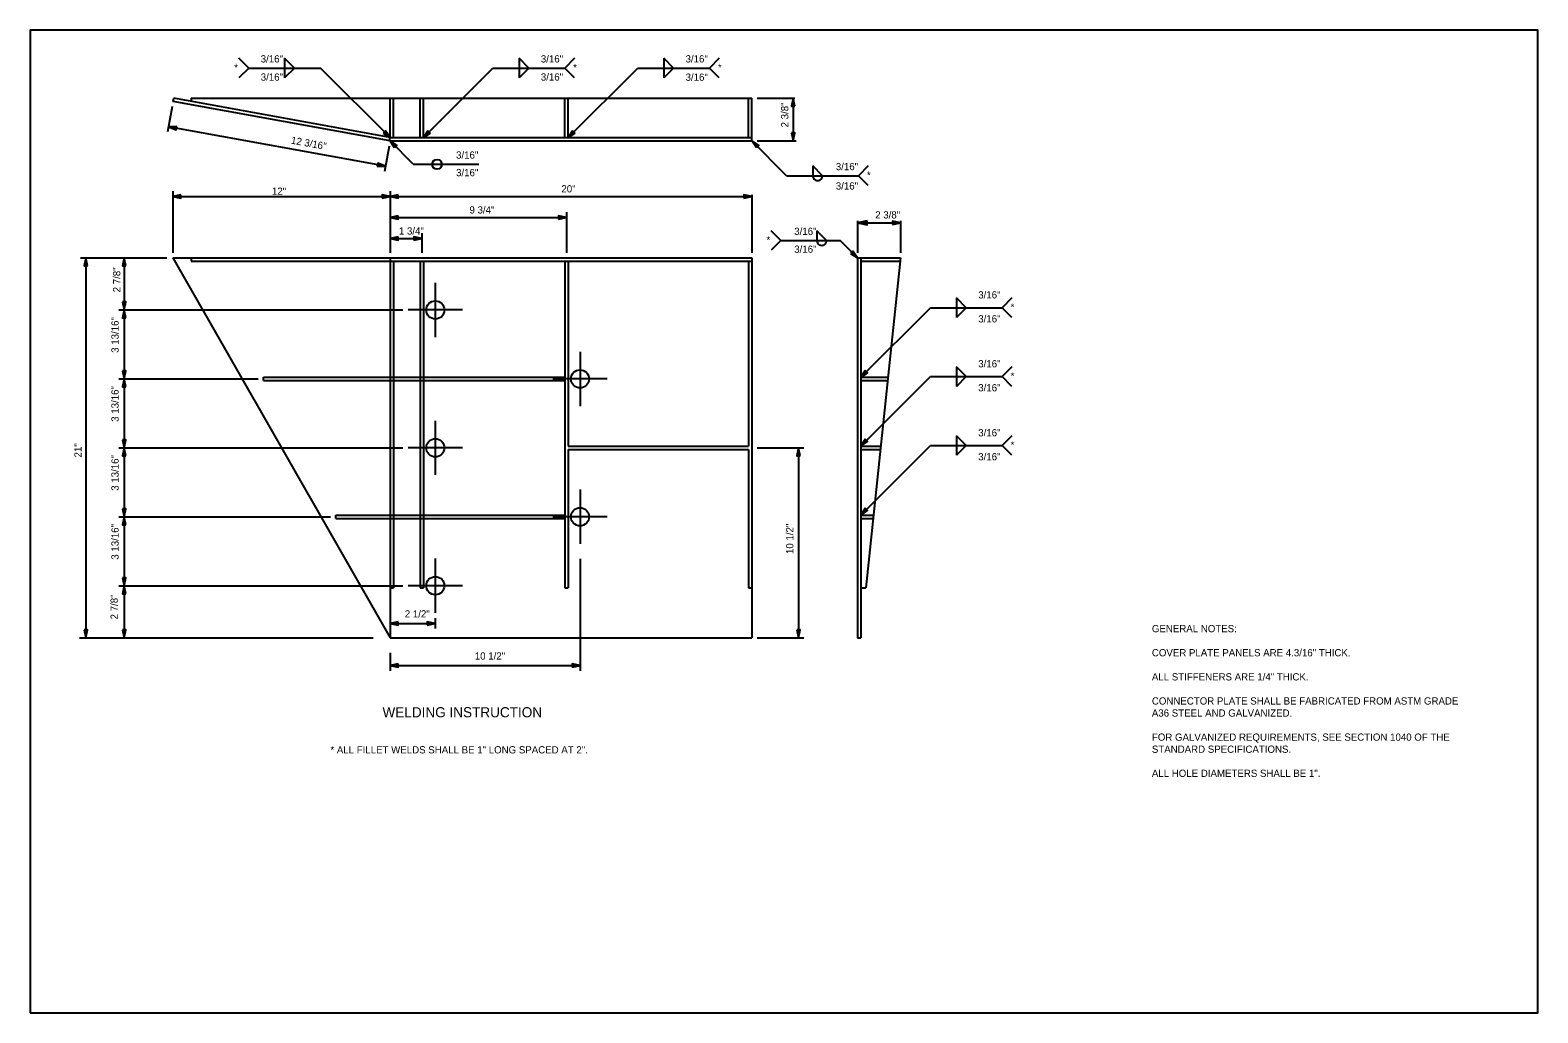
# Model space of a CAD drawing. Extents: x -439.1 to -407.9, y -458.1 to -437.7.
import ezdxf

# ---------------------------------------------------------------- set-up
doc = ezdxf.new("R2010")
doc.units = 0
for name, color, linetype in [('Common-Notes', 7, 'Continuous'), ('Draft_Named_Boundary', 7, 'Continuous'), ('Level 4', 7, 'Continuous'), ('Level 45', 7, 'Continuous')]:
    doc.layers.add(name, color=color, linetype=linetype)

msp = doc.modelspace()

# ---------------------------------------------------------------- linework, layer by layer
at = {"layer": 'Draft_Named_Boundary'}
msp.add_lwpolyline([(-439.109, -458.051), (-407.859, -458.051), (-407.859, -437.676), (-439.109, -437.676)], close=True, dxfattribs=at)
at = {"layer": 'Level 4'}
for p, q in [((-434.579, -438.462), (-434.781, -438.26)), ((-433.835, -438.26), (-433.835, -438.664)), ((-433.633, -438.462), (-433.835, -438.26)), ((-428.974, -438.26), (-428.974, -438.664)), ((-428.772, -438.462), (-428.974, -438.26)), ((-427.827, -438.26), (-428.028, -438.462)), ((-425.974, -438.26), (-425.974, -438.664)), ((-425.772, -438.462), (-425.974, -438.26)), ((-424.827, -438.26), (-425.028, -438.462)), ((-434.579, -438.462), (-434.781, -438.664)), ((-434.579, -438.462), (-433.091, -438.462)), ((-433.633, -438.462), (-433.835, -438.664)), ((-431.649, -439.903), (-433.091, -438.462)), ((-430.958, -439.903), (-429.516, -438.462)), ((-429.516, -438.462), (-428.028, -438.462)), ((-428.772, -438.462), (-428.974, -438.664)), ((-427.827, -438.664), (-428.028, -438.462)), ((-427.958, -439.903), (-426.516, -438.462)), ((-426.516, -438.462), (-425.028, -438.462)), ((-425.772, -438.462), (-425.974, -438.664)), ((-424.827, -438.664), (-425.028, -438.462)), ((-436.165, -439.262), (-436.26, -439.786)), ((-436.145, -439.154), (-436.133, -439.087)), ((-431.649, -439.973), (-436.145, -439.154)), ((-431.649, -439.903), (-436.133, -439.087)), ((-435.774, -439.083), (-424.149, -439.083)), ((-435.774, -439.083), (-435.774, -439.152)), ((-431.649, -439.903), (-431.649, -439.083)), ((-431.579, -439.903), (-431.579, -439.083)), ((-431.028, -439.903), (-431.028, -439.083)), ((-430.958, -439.903), (-430.958, -439.083)), ((-428.028, -439.903), (-428.028, -439.083)), ((-427.958, -439.903), (-427.958, -439.083)), ((-424.22, -439.903), (-424.22, -439.083)), ((-424.149, -439.973), (-424.149, -439.083)), ((-424.041, -439.083), (-423.257, -439.083)), ((-423.291, -439.083), (-423.291, -439.973)), ((-431.745, -440.498), (-436.241, -439.679)), ((-431.662, -439.971), (-431.649, -439.903)), ((-431.649, -439.903), (-424.149, -439.903)), ((-431.649, -439.973), (-424.149, -439.973)), ((-431.167, -440.456), (-431.649, -439.973)), ((-423.429, -440.694), (-424.149, -439.973)), ((-424.041, -439.973), (-423.231, -439.973)), ((-431.669, -440.081), (-431.764, -440.605)), ((-431.167, -440.456), (-429.812, -440.456)), ((-422.887, -440.492), (-422.887, -440.694)), ((-422.685, -440.694), (-422.887, -440.492)), ((-421.739, -440.492), (-421.941, -440.694)), ((-423.429, -440.694), (-421.941, -440.694)), ((-421.739, -440.896), (-421.941, -440.694)), ((-436.149, -441.015), (-436.149, -442.29)), ((-436.149, -441.124), (-431.649, -441.124)), ((-431.649, -441.015), (-431.649, -442.29)), ((-431.649, -441.124), (-424.149, -441.124)), ((-424.149, -441.089), (-424.149, -442.29)), ((-431.649, -441.559), (-427.993, -441.559)), ((-427.993, -441.45), (-427.993, -442.29)), ((-423.547, -442.038), (-423.749, -441.836)), ((-422.803, -441.836), (-422.803, -442.038)), ((-422.601, -442.038), (-422.803, -441.836)), ((-421.962, -441.627), (-421.962, -442.29)), ((-421.962, -441.668), (-421.072, -441.668)), ((-421.072, -441.627), (-421.072, -442.29)), ((-431.649, -441.995), (-430.993, -441.995)), ((-430.993, -441.886), (-430.993, -442.29)), ((-423.547, -442.038), (-423.749, -442.24)), ((-423.547, -442.038), (-422.323, -442.038)), ((-421.962, -442.399), (-422.323, -442.038)), ((-438.065, -442.399), (-436.275, -442.399)), ((-437.956, -442.399), (-437.956, -450.274)), ((-437.159, -442.399), (-437.159, -443.477)), ((-436.149, -442.399), (-431.649, -442.399)), ((-436.149, -442.399), (-431.649, -450.274)), ((-435.774, -442.399), (-435.774, -442.469)), ((-435.774, -442.469), (-431.649, -442.469)), ((-431.649, -442.399), (-424.149, -442.399)), ((-431.649, -442.399), (-431.649, -450.274)), ((-431.649, -442.469), (-424.149, -442.469)), ((-431.579, -442.469), (-431.579, -449.242)), ((-431.028, -442.469), (-431.028, -449.242)), ((-430.958, -442.469), (-430.958, -449.242)), ((-428.028, -442.469), (-428.028, -449.242)), ((-427.958, -442.469), (-427.958, -446.301)), ((-424.22, -442.469), (-424.22, -446.301)), ((-424.149, -442.399), (-424.149, -450.274)), ((-421.962, -442.399), (-421.962, -450.274)), ((-421.962, -442.399), (-421.072, -442.399)), ((-421.892, -442.399), (-421.892, -450.274)), ((-421.892, -442.469), (-421.072, -442.469)), ((-421.072, -442.399), (-421.785, -449.242)), ((-430.712, -442.914), (-430.712, -444.039)), ((-421.892, -444.871), (-420.45, -443.43)), ((-420.45, -443.43), (-418.962, -443.43)), ((-419.908, -443.228), (-419.908, -443.632)), ((-419.706, -443.43), (-419.908, -443.228)), ((-419.706, -443.43), (-419.908, -443.632)), ((-418.761, -443.228), (-418.962, -443.43)), ((-418.761, -443.632), (-418.962, -443.43)), ((-437.268, -443.477), (-431.383, -443.477)), ((-437.159, -443.477), (-437.159, -444.907)), ((-430.149, -443.477), (-431.274, -443.477)), ((-427.712, -444.344), (-427.712, -445.469)), ((-419.908, -444.657), (-419.908, -445.061)), ((-419.706, -444.859), (-419.908, -444.657)), ((-418.761, -444.657), (-418.962, -444.859)), ((-437.268, -444.907), (-434.383, -444.907)), ((-437.159, -444.907), (-437.159, -446.336)), ((-434.274, -444.871), (-428.028, -444.871)), ((-434.274, -444.942), (-434.274, -444.871)), ((-434.274, -444.942), (-428.028, -444.942)), ((-427.149, -444.907), (-428.274, -444.907)), ((-421.892, -446.301), (-420.45, -444.859)), ((-421.892, -444.871), (-421.329, -444.871)), ((-421.892, -444.942), (-421.329, -444.942)), ((-420.45, -444.859), (-418.962, -444.859)), ((-419.706, -444.859), (-419.908, -445.061)), ((-418.761, -445.061), (-418.962, -444.859)), ((-430.712, -445.774), (-430.712, -446.899)), ((-419.908, -446.087), (-419.908, -446.491)), ((-419.706, -446.289), (-419.908, -446.087)), ((-418.761, -446.087), (-418.962, -446.289)), ((-437.268, -446.336), (-431.383, -446.336)), ((-437.159, -446.336), (-437.159, -447.766)), ((-430.149, -446.336), (-431.274, -446.336)), ((-427.958, -446.301), (-424.22, -446.301)), ((-427.958, -446.371), (-424.22, -446.371)), ((-427.958, -446.371), (-427.958, -449.242)), ((-424.22, -446.371), (-424.22, -449.242)), ((-424.041, -446.336), (-423.074, -446.336)), ((-423.183, -446.336), (-423.183, -450.274)), ((-421.892, -447.73), (-420.45, -446.289)), ((-421.892, -446.301), (-421.478, -446.301)), ((-421.892, -446.371), (-421.485, -446.371)), ((-420.45, -446.289), (-418.962, -446.289)), ((-419.706, -446.289), (-419.908, -446.491)), ((-418.761, -446.491), (-418.962, -446.289)), ((-427.712, -447.203), (-427.712, -448.328)), ((-437.268, -447.766), (-432.883, -447.766)), ((-437.159, -447.766), (-437.159, -449.195)), ((-432.774, -447.73), (-428.028, -447.73)), ((-432.774, -447.801), (-432.774, -447.73)), ((-432.774, -447.801), (-428.028, -447.801)), ((-427.149, -447.766), (-428.274, -447.766)), ((-421.892, -447.73), (-421.627, -447.73)), ((-421.892, -447.801), (-421.635, -447.801)), ((-430.712, -448.633), (-430.712, -449.758)), ((-427.712, -448.64), (-427.712, -450.959)), ((-437.268, -449.195), (-431.383, -449.195)), ((-437.159, -449.195), (-437.159, -450.274)), ((-431.649, -449.242), (-431.579, -449.242)), ((-430.149, -449.195), (-431.274, -449.195)), ((-431.028, -449.242), (-430.958, -449.242)), ((-428.028, -449.242), (-427.958, -449.242)), ((-424.22, -449.242), (-424.149, -449.242)), ((-421.892, -449.242), (-421.785, -449.242)), ((-431.649, -449.975), (-430.712, -449.975)), ((-430.712, -449.866), (-430.712, -450.084)), ((-438.084, -450.275), (-431.997, -450.275)), ((-431.649, -450.274), (-424.149, -450.274)), ((-424.041, -450.274), (-423.074, -450.274)), ((-421.962, -450.274), (-421.892, -450.274)), ((-431.649, -450.586), (-431.649, -450.959)), ((-431.649, -450.85), (-427.712, -450.85))]:
    msp.add_line(p, q, dxfattribs=at)
for points in [[(-423.257, -439.249), (-423.291, -439.083), (-423.326, -439.249)], [(-436.072, -439.675), (-436.241, -439.679), (-436.084, -439.742)], [(-431.791, -439.81), (-431.649, -439.903), (-431.742, -439.762)], [(-431.556, -440.115), (-431.649, -439.973), (-431.508, -440.066)], [(-430.865, -439.762), (-430.958, -439.903), (-430.816, -439.81)], [(-427.865, -439.762), (-427.958, -439.903), (-427.816, -439.81)], [(-424.056, -440.115), (-424.149, -439.973), (-424.008, -440.066)], [(-423.326, -439.808), (-423.291, -439.973), (-423.257, -439.808)], [(-431.914, -440.502), (-431.745, -440.498), (-431.902, -440.434)], [(-435.983, -441.089), (-436.149, -441.124), (-435.983, -441.158)], [(-431.815, -441.158), (-431.649, -441.124), (-431.815, -441.089)], [(-431.483, -441.089), (-431.649, -441.124), (-431.483, -441.158)], [(-424.315, -441.158), (-424.149, -441.124), (-424.315, -441.089)], [(-431.483, -441.525), (-431.649, -441.559), (-431.483, -441.594)], [(-428.159, -441.594), (-427.993, -441.559), (-428.159, -441.525)], [(-421.763, -441.627), (-421.962, -441.668), (-421.763, -441.709)], [(-421.238, -441.703), (-421.072, -441.668), (-421.238, -441.634)], [(-431.483, -441.96), (-431.649, -441.995), (-431.483, -442.029)], [(-431.159, -442.029), (-430.993, -441.995), (-431.159, -441.96)], [(-437.921, -442.565), (-437.956, -442.399), (-437.99, -442.565)], [(-437.124, -442.565), (-437.159, -442.399), (-437.193, -442.565)], [(-422.104, -442.306), (-421.962, -442.399), (-422.055, -442.257)], [(-437.193, -443.311), (-437.159, -443.477), (-437.124, -443.311)], [(-437.124, -443.643), (-437.159, -443.477), (-437.193, -443.643)], [(-437.193, -444.741), (-437.159, -444.907), (-437.124, -444.741)], [(-437.124, -445.073), (-437.159, -444.907), (-437.193, -445.073)], [(-421.799, -444.73), (-421.892, -444.871), (-421.75, -444.778)], [(-437.193, -446.17), (-437.159, -446.336), (-437.124, -446.17)], [(-421.799, -446.159), (-421.892, -446.301), (-421.75, -446.208)], [(-437.124, -446.502), (-437.159, -446.336), (-437.193, -446.502)], [(-423.148, -446.502), (-423.183, -446.336), (-423.217, -446.502)], [(-437.193, -447.6), (-437.159, -447.766), (-437.124, -447.6)], [(-437.124, -447.932), (-437.159, -447.766), (-437.193, -447.932)], [(-421.799, -447.589), (-421.892, -447.73), (-421.75, -447.637)], [(-437.193, -449.029), (-437.159, -449.195), (-437.124, -449.029)], [(-437.124, -449.361), (-437.159, -449.195), (-437.193, -449.361)], [(-431.483, -449.941), (-431.649, -449.975), (-431.483, -450.01)], [(-430.878, -450.01), (-430.712, -449.975), (-430.878, -449.941)], [(-437.99, -450.108), (-437.956, -450.274), (-437.921, -450.108)], [(-437.193, -450.108), (-437.159, -450.274), (-437.124, -450.108)], [(-423.217, -450.108), (-423.183, -450.274), (-423.148, -450.108)], [(-431.483, -450.815), (-431.649, -450.85), (-431.483, -450.884)], [(-427.878, -450.884), (-427.712, -450.85), (-427.878, -450.815)]]:
    msp.add_lwpolyline(points, close=True, dxfattribs=at)
for centre, radius in [((-430.674, -440.456), 0.101), ((-430.712, -443.477), 0.188), ((-427.712, -444.907), 0.188), ((-430.712, -446.336), 0.188), ((-427.712, -447.766), 0.188), ((-430.712, -449.195), 0.188)]:
    msp.add_circle(centre, radius, dxfattribs=at)
for centre in [(-422.786, -440.694), (-422.702, -442.038)]:
    msp.add_arc(centre, 0.101, 179.9941, 0.003, dxfattribs=at)

# ---------------------------------------------------------------- texts
at = {"layer": 'Common-Notes'}
for s, height, p in [('GENERAL NOTES:', 0.15, (-415.859, -450.159)), ('COVER PLATE PANELS ARE 4.3/16" THICK.', 0.15, (-415.859, -450.659)), ('ALL STIFFENERS ARE 1/4" THICK.', 0.15, (-415.859, -451.159)), ('CONNECTOR PLATE SHALL BE FABRICATED FROM ASTM GRADE ', 0.15, (-415.859, -451.659)), ('WELDING INSTRUCTION', 0.21, (-431.806, -451.923)), ('A36 STEEL AND GALVANIZED.', 0.15, (-415.859, -451.909)), ('FOR GALVANIZED REQUIREMENTS, SEE SECTION 1040 OF THE ', 0.15, (-415.859, -452.409)), ('* ALL FILLET WELDS SHALL BE 1" LONG SPACED AT 2".', 0.15, (-432.886, -452.672)), ('STANDARD SPECIFICATIONS.', 0.15, (-415.859, -452.659)), ('ALL HOLE DIAMETERS SHALL BE 1".', 0.15, (-415.859, -453.159))]:
    msp.add_text(s, height=height, dxfattribs=at).set_placement(p)
at = {"layer": 'Level 4'}
for p in [(-434.879, -438.524), (-427.856, -438.525), (-424.853, -438.523), (-421.766, -440.755), (-423.848, -442.099), (-418.787, -443.491), (-418.787, -444.92), (-418.787, -446.35)]:
    msp.add_text('*', height=0.15, dxfattribs=at).set_placement(p)
at = {"layer": 'Level 45'}
for s, p in [('3/16"', (-434.33, -438.346)), ('3/16"', (-428.524, -438.346)), ('3/16"', (-425.524, -438.346)), ('3/16"', (-434.33, -438.724)), ('3/16"', (-428.524, -438.722)), ('3/16"', (-425.524, -438.726)), ('3/16"', (-430.281, -440.34)), ('3/16"', (-430.281, -440.705)), ('3/16"', (-422.41, -440.579)), ('20"', (-428.098, -441.04)), ('3/16"', (-422.41, -440.981)), ('12"', (-434.098, -441.09)), ('9 3/4"', (-430.003, -441.478)), ('2 3/8"', (-421.594, -441.581)), ('1 3/4"', (-431.466, -441.915)), ('3/16"', (-423.272, -441.922)), ('3/16"', (-423.272, -442.292)), ('3/16"', (-419.458, -443.239)), ('3/16"', (-419.458, -443.736)), ('3/16"', (-419.458, -444.668)), ('3/16"', (-419.458, -445.165)), ('3/16"', (-419.458, -446.098)), ('3/16"', (-419.458, -446.595)), ('2 1/2"', (-431.344, -449.853)), ('10 1/2"', (-429.893, -450.727))]:
    msp.add_text(s, height=0.15, dxfattribs=at).set_placement(p)
for s, rotation, p in [('2 3/8"', 90, (-423.393, -439.692)), ('12 3/16"', 349.6415, (-433.711, -440.027)), ('2 7/8"', 90, (-437.24, -443.112)), ('3 13/16"', 90, (-437.275, -444.366)), ('3 13/16"', 90, (-437.275, -445.796)), ('21"', 90, (-438.043, -446.535)), ('3 13/16"', 90, (-437.275, -447.226)), ('3 13/16"', 90, (-437.275, -448.655)), ('10 1/2"', 90, (-423.291, -448.537)), ('2 7/8"', 90, (-437.293, -449.893))]:
    msp.add_text(s, height=0.15, rotation=rotation, dxfattribs=at).set_placement(p)

doc.saveas('drawing.dxf')
